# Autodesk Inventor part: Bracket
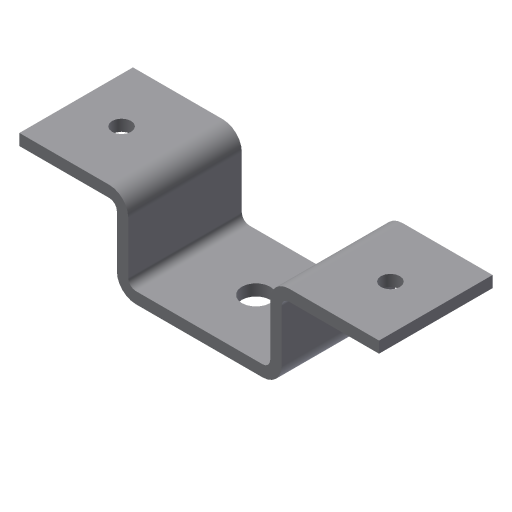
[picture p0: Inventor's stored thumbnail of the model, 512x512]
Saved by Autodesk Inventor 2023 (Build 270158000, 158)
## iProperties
Part Number: Bracket
Document SubType Name: Modeling
Created: 2003-01
Designer: Owner
Density: 1 g/cm^3
Material: Generic
Appearance: Default
Control State: 0
Master: False
Checked Out: False
Shininess: 64.0
Length Units: 11269
Angle Units: 11279
Time Units: 11290
Mass Units: 11283
Length Display Precision: 3
Angle Display Precision: 2
Compacted: True
Density: 0.0
Volumn: 0.0
Area: 0.0
PropertySet Name: Model Information
Author: Owner
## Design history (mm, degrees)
sketch "Sketch2"
  geometry: L1 (487.39, 112.858)-(199.89, 112.858); L2 (199.89, 112.858)-(199.89, -95.142); L3 (199.89, -95.142)-(-175.11, -95.142); L4 (-175.11, -95.142)-(-175.11, 112.858); L5 (-175.11, 112.858)-(-462.61, 112.858); L6 (-462.61, 82.858)-(-205.11, 82.858); L7 (-205.11, 82.858)-(-205.11, -125.142); L8 (-205.11, -125.142)-(229.89, -125.142); L9 (229.89, -125.142)-(229.89, 82.858); L10 (229.89, 82.858)-(487.39, 82.858); L11 (487.39, 112.858)-(487.39, 82.858); L12 (-462.61, 112.858)-(-462.61, 82.858)
  constraints: 24 end point, 5 parallel, 3 perpendicular, 2 collinear, 2 equal length, 1 horizontal, 4 other
  dimensions: "d0" = 375 distance between parallel lines of L4 L2; "d1" = 950 distance of L5.end L1.start; "d2" = 30 distance between parallel lines of L1 L10; "d3" = 238 distance between parallel lines of L5 L8
extrude "Extrusion1" new body sketch "Sketch2" stored distance "d4" = 300; taper "d5" = 0 deg
fillet "Fillet1" dims "d6" = 20
fillet "Fillet2" dims "d7" = 50
sketch "Sketch3"
  geometry: L1 (237.5, 300)-(0, 300) reference; L2 (0, 300)-(0, 0) reference; 1 further point
  dimensions: "d8" = 120 distance from line of L2 point (120, 150); "d9" = 150 distance from line of L1 point (120, 150)
hole "Hole1" sketch "Sketch3" at (120, 150) diameter "d10" = 50; stored, may be unused: countersink angle "d14" = 82 deg, drill point angle "d16" = 118 deg; dims "d11" = 6, "d12" = 4, "d13" = 2, "d15" = 8
pattern_linear "Rectangular Pattern1" dims "d19" = 710
sketch "Sketch4"
  geometry: L1 (0, -300)-(335, -300) reference; 1 further point
  dimensions: "d20" = 150 distance from line of L1 point (167.5, -150)
hole "Hole2" sketch "Sketch4" at (167.5, -150) diameter "d21" = 75; stored, may be unused: countersink angle "d25" = 82 deg, drill point angle "d27" = 118 deg; dims "d22" = 6, "d23" = 4, "d24" = 2, "d26" = 8
body "Solid1"
